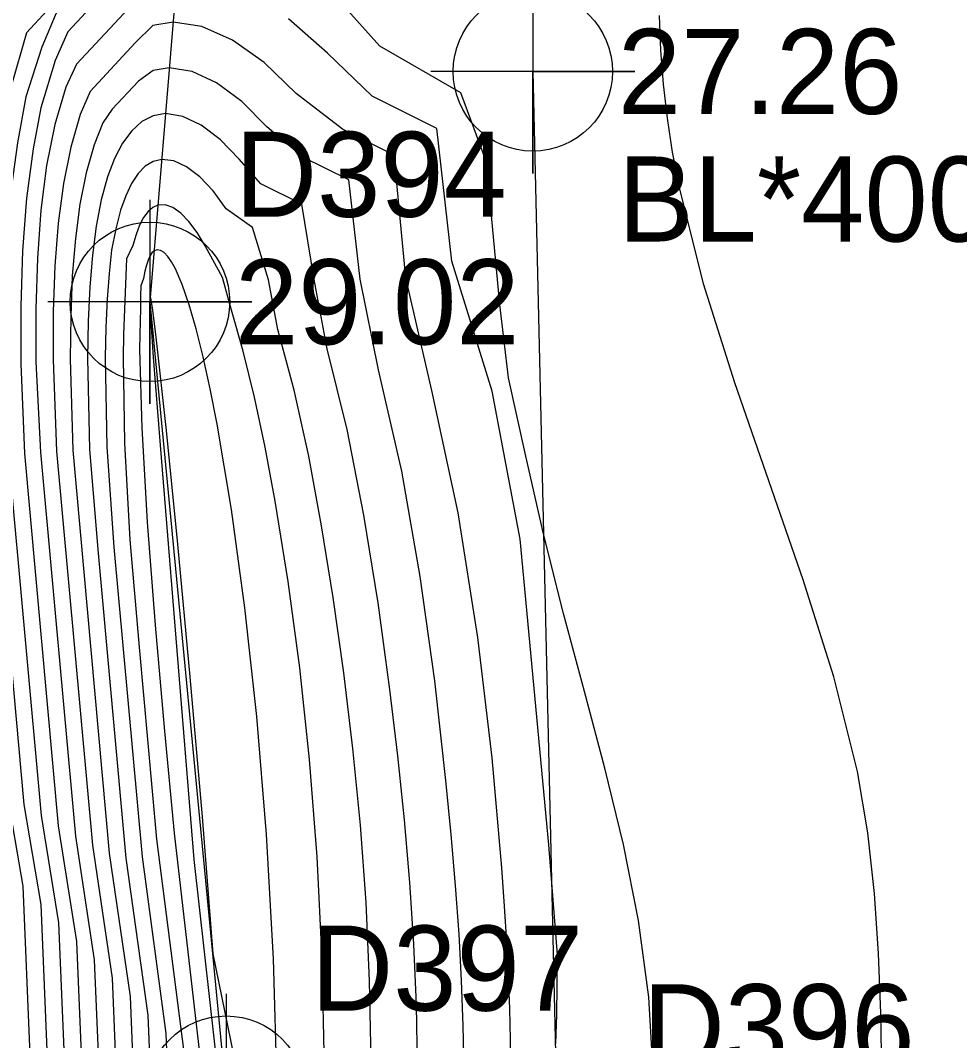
# Model space of a CAD drawing. Extents: x 2356077 to 2359823, y 225951 to 227822.
# Drawn here: x 2356587.63 to 2356615.24, y 227196.5 to 227226.48 of the extents above; entities that cross this region are included whole.
import ezdxf

# ---------------------------------------------------------------- set-up
doc = ezdxf.new("R2010")
doc.units = 0
for name, color, linetype in [('DTM Contours Major', 7, 'Continuous'), ('DTM Contours Minor', 7, 'Continuous'), ('Exist DTM Breakline', 7, 'Continuous'), ('Exist DTM Breakline Cogo Comment', 7, 'Continuous'), ('Exist DTM Breakline Cogo Elevation', 7, 'Continuous'), ('Exist DTM Breakline Cogo Number', 7, 'Continuous'), ('Exist DTM Breakline Cogo Point CELL', 7, 'Continuous')]:
    doc.layers.add(name, color=color, linetype=linetype)

msp = doc.modelspace()

# ---------------------------------------------------------------- linework, layer by layer
at = {"layer": 'DTM Contours Major'}
for points in [[(2356589.008, 227227.424), (2356587.813, 227226.121), (2356587.349, 227224.513), (2356587.22, 227221.462), (2356587.053, 227219.76), (2356586.932, 227217.945), (2356586.884, 227216.067), (2356586.915, 227213.59), (2356587.041, 227211.067), (2356587.733, 227203.437), (2356588.228, 227200.499), (2356588.6, 227191.455)], [(2356600.672, 227195.646), (2356600.65, 227196.936), (2356600.602, 227198.26), (2356600.527, 227199.63), (2356600.425, 227201.059), (2356600.296, 227202.56), (2356600.142, 227204.144), (2356599.813, 227207.067), (2356599.387, 227210.142), (2356598.842, 227213.235), (2356598.157, 227216.213), (2356597.616, 227218.881), (2356597.282, 227221.794), (2356595.936, 227222.463), (2356594.88, 227223.351), (2356594.139, 227224.1), (2356593.397, 227224.646), (2356592.68, 227224.979), (2356592.008, 227225.086), (2356591.532, 227225.01), (2356591.099, 227224.698), (2356590.332, 227223.875), (2356590.055, 227223.469), (2356589.796, 227222.822), (2356589.562, 227222.003), (2356589.38, 227221.084), (2356589.247, 227220.072), (2356589.157, 227218.973), (2356589.109, 227217.793), (2356589.096, 227216.538), (2356589.17, 227213.847), (2356590.244, 227202.01), (2356590.855, 227197.789), (2356591.048, 227193.105)], [(2356594.167, 227194.791), (2356593.296, 227199.05), (2356592.981, 227203.077), (2356592.625, 227207.194), (2356592.262, 227211.085), (2356591.928, 227214.43), (2356591.625, 227217.171), (2356591.522, 227217.968), (2356591.473, 227218.274), (2356591.452, 227218.363), (2356591.444, 227218.376), (2356591.436, 227218.355), (2356591.434, 227218.196), (2356591.438, 227218.088), (2356591.534, 227216.589), (2356591.735, 227213.999), (2356592.355, 227206.4), (2356592.725, 227201.818), (2356593.483, 227195.078)]]:
    msp.add_lwpolyline(points, dxfattribs=at)
at = {"layer": 'DTM Contours Minor'}
for points in [[(2356591.548, 227228.857), (2356589.021, 227226.143), (2356588.652, 227225.301), (2356588.227, 227223.908), (2356588.005, 227222.711), (2356587.812, 227221.256), (2356587.693, 227219.71), (2356587.64, 227218.083), (2356587.643, 227216.386), (2356587.749, 227213.755), (2356588.742, 227202.809), (2356589.279, 227199.415), (2356589.579, 227192.115)], [(2356591.515, 227227.595), (2356589.277, 227225.193), (2356588.964, 227224.524), (2356588.641, 227223.425), (2356588.4, 227222.215), (2356588.232, 227220.902), (2356588.129, 227219.497), (2356588.084, 227218.009), (2356588.088, 227216.447), (2356588.222, 227213.794), (2356589.246, 227202.509), (2356589.804, 227198.873), (2356590.069, 227192.445)], [(2356588.735, 227226.81), (2356588.262, 227225.693), (2356587.789, 227224.237), (2356587.541, 227222.884), (2356587.331, 227221.329), (2356587.205, 227219.688), (2356587.153, 227217.971), (2356587.162, 227216.187), (2356587.282, 227213.652), (2356588.238, 227203.117), (2356588.753, 227199.957), (2356589.09, 227191.785)], [(2356606.244, 227195.395), (2356606.101, 227197.775), (2356605.801, 227200.025), (2356605.359, 227202.263), (2356604.817, 227204.504), (2356604.216, 227206.762), (2356603.599, 227209.053), (2356603.007, 227211.392), (2356602.489, 227213.679), (2356601.984, 227215.975), (2356601.726, 227218.137), (2356601.332, 227222.317), (2356600.577, 227224.357), (2356598.199, 227225.727), (2356597.086, 227226.964)], [(2356587.04, 227226.516), (2356586.907, 227224.774), (2356586.829, 227222.918), (2356586.664, 227221.139), (2356586.498, 227219.431), (2356586.413, 227217.642), (2356586.398, 227215.777), (2356586.457, 227213.466), (2356586.581, 227211.092), (2356586.781, 227208.68), (2356587.22, 227203.836), (2356587.702, 227201.041), (2356588.11, 227191.125)], [(2356602.047, 227195.656), (2356602.04, 227196.527), (2356602.018, 227197.434), (2356601.981, 227198.385), (2356601.929, 227199.387), (2356601.863, 227200.449), (2356601.781, 227201.579), (2356601.496, 227204.807), (2356601.078, 227208.348), (2356600.498, 227212.01), (2356599.724, 227215.603), (2356598.959, 227218.913), (2356598.62, 227222.522), (2356597.1, 227223.284), (2356595.733, 227224.332), (2356594.801, 227225.244), (2356593.867, 227225.906), (2356592.963, 227226.306), (2356592.119, 227226.431), (2356591.524, 227226.333), (2356591.001, 227225.819), (2356589.677, 227224.397), (2356589.389, 227223.712), (2356589.109, 227222.753), (2356588.896, 227221.687), (2356588.744, 227220.521), (2356588.646, 227219.264), (2356588.597, 227217.923), (2356588.592, 227216.507), (2356588.696, 227213.826), (2356589.747, 227202.24), (2356590.33, 227198.331), (2356590.558, 227192.775)], [(2356603.369, 227196.41), (2356603.398, 227197.255), (2356603.414, 227198.123), (2356603.419, 227199.017), (2356603.167, 227202.256), (2356602.322, 227211.231), (2356601.5, 227215.581), (2356600.314, 227219.408), (2356599.875, 227223.306), (2356597.971, 227224.252), (2356596.66, 227225.521), (2356595.515, 227226.532)], [(2356615.934, 227181.068), (2356614.844, 227183.13), (2356614.067, 227185.234), (2356613.549, 227187.367), (2356613.233, 227189.511), (2356613.065, 227191.651), (2356612.989, 227193.773), (2356612.922, 227197.303), (2356612.86, 227199.058), (2356612.744, 227200.82), (2356612.545, 227202.601), (2356612.237, 227204.41), (2356611.544, 227207.191), (2356610.645, 227210.038), (2356608.63, 227215.835), (2356607.714, 227218.737), (2356606.993, 227221.611), (2356606.803, 227222.612), (2356606.65, 227223.61), (2356606.535, 227224.609), (2356606.456, 227225.612), (2356606.415, 227226.623)], [(2356599.306, 227195.766), (2356599.272, 227197.547), (2356599.196, 227199.335), (2356599.077, 227201.144), (2356598.919, 227202.985), (2356598.723, 227204.871), (2356598.492, 227206.813), (2356598.145, 227209.364), (2356597.73, 227211.94), (2356597.235, 227214.457), (2356596.645, 227216.83), (2356596.271, 227218.865), (2356595.902, 227221.08), (2356594.701, 227221.676), (2356594.064, 227222.401), (2356593.503, 227222.983), (2356592.944, 227223.406), (2356592.404, 227223.662), (2356591.897, 227223.742), (2356591.536, 227223.677), (2356591.205, 227223.507), (2356590.904, 227223.237), (2356590.635, 227222.873), (2356590.398, 227222.421), (2356590.195, 227221.888), (2356590.007, 227221.206), (2356589.859, 227220.436), (2356589.748, 227219.582), (2356589.67, 227218.648), (2356589.624, 227217.639), (2356589.608, 227216.559), (2356589.664, 227213.885), (2356589.911, 227210.928), (2356590.734, 227201.861), (2356591.381, 227197.247), (2356591.538, 227193.435)], [(2356597.942, 227195.909), (2356597.898, 227198.25), (2356597.791, 227200.556), (2356597.625, 227202.832), (2356597.405, 227205.08), (2356597.137, 227207.307), (2356596.825, 227209.517), (2356596.487, 227211.625), (2356596.107, 227213.673), (2356595.679, 227215.614), (2356595.199, 227217.4), (2356594.925, 227218.857), (2356594.456, 227220.398), (2356593.682, 227220.944), (2356593.294, 227221.47), (2356592.901, 227221.885), (2356592.513, 227222.182), (2356592.138, 227222.355), (2356591.785, 227222.397), (2356591.533, 227222.336), (2356591.301, 227222.196), (2356591.088, 227221.979), (2356590.897, 227221.69), (2356590.726, 227221.331), (2356590.578, 227220.906), (2356590.439, 227220.359), (2356590.312, 227219.731), (2356590.243, 227219.047), (2356590.181, 227218.286), (2356590.142, 227217.46), (2356590.125, 227216.572), (2356590.172, 227213.951), (2356590.382, 227210.996), (2356591.207, 227201.896), (2356591.906, 227196.705), (2356592.027, 227193.765)], [(2356596.573, 227195.69), (2356596.503, 227198.877), (2356596.351, 227201.9), (2356596.128, 227204.76), (2356595.842, 227207.456), (2356595.504, 227209.987), (2356595.122, 227212.354), (2356594.829, 227213.935), (2356594.516, 227215.412), (2356594.184, 227216.763), (2356593.832, 227217.968), (2356593.572, 227218.925), (2356593.061, 227219.856), (2356592.824, 227220.248), (2356592.584, 227220.569), (2356592.345, 227220.814), (2356592.11, 227220.979), (2356591.885, 227221.059), (2356591.674, 227221.052), (2356591.523, 227220.984), (2356591.382, 227220.862), (2356591.253, 227220.688), (2356591.136, 227220.463), (2356591.032, 227220.188), (2356590.94, 227219.865), (2356590.754, 227219.47), (2356590.66, 227217.252), (2356590.647, 227216.576), (2356590.693, 227214.057), (2356590.847, 227211.212), (2356591.124, 227208.061), (2356591.636, 227202.417), (2356592.432, 227196.162)], [(2356595.179, 227195.104), (2356595.075, 227198.901), (2356594.87, 227202.559), (2356594.583, 227206.019), (2356594.232, 227209.221), (2356593.837, 227212.106), (2356593.414, 227214.616), (2356593.21, 227215.655), (2356593.005, 227216.59), (2356592.8, 227217.416), (2356592.595, 227218.127), (2356592.391, 227218.717), (2356592.189, 227219.179), (2356592.076, 227219.383), (2356591.964, 227219.543), (2356591.856, 227219.656), (2356591.752, 227219.722), (2356591.654, 227219.74), (2356591.563, 227219.707), (2356591.498, 227219.647), (2356591.438, 227219.557), (2356591.383, 227219.436), (2356591.334, 227219.287), (2356591.29, 227219.108), (2356591.251, 227218.9), (2356591.172, 227218.68), (2356591.16, 227218.381), (2356591.162, 227218.01), (2356591.147, 227217.644), (2356591.138, 227217.249), (2356591.135, 227216.822), (2356591.197, 227214.506), (2356591.361, 227211.737), (2356591.595, 227208.703), (2356591.868, 227205.593), (2356592.149, 227202.595), (2356592.957, 227195.62)]]:
    msp.add_lwpolyline(points, dxfattribs=at)
at = {"layer": 'Exist DTM Breakline'}
for points in [[(2356575.82, 227148.639), (2356572.681, 227182.58), (2356573.963, 227212.061), (2356577.748, 227240.207), (2356581.287, 227243.662), (2356587.377, 227239.444), (2356592.648, 227232.822), (2356591.439, 227218.21), (2356593.678, 227194.877), (2356594.225, 227153.117)], [(2356602.695, 227224.982), (2356603.426, 227193.155), (2356599.546, 227163.669)]]:
    msp.add_lwpolyline(points, dxfattribs=at)
at = {"layer": 'Exist DTM Breakline Cogo Point CELL'}
for points in [[(2356602.695, 227227.982), (2356602.695, 227221.982), (2356602.695, 227224.982), (2356605.695, 227224.982), (2356599.695, 227224.982)], [(2356591.439, 227221.21), (2356591.439, 227215.21), (2356591.439, 227218.21), (2356594.439, 227218.21), (2356588.439, 227218.21)], [(2356593.678, 227197.877), (2356593.678, 227191.877), (2356593.678, 227194.877), (2356596.678, 227194.877), (2356590.678, 227194.877)]]:
    msp.add_lwpolyline(points, dxfattribs=at)
for centre in [(2356602.695, 227224.982), (2356591.439, 227218.21), (2356593.678, 227194.877)]:
    msp.add_circle(centre, 2.344, dxfattribs=at)

# ---------------------------------------------------------------- texts
at = {"layer": 'Exist DTM Breakline Cogo Comment'}
msp.add_text('BL*40052', height=2.5, dxfattribs=at).set_placement((2356605.195, 227219.983))
at = {"layer": 'Exist DTM Breakline Cogo Elevation'}
for s, p in [('27.26', (2356605.195, 227223.733)), ('29.02', (2356593.939, 227216.96))]:
    msp.add_text(s, height=2.5, dxfattribs=at).set_placement(p)
at = {"layer": 'Exist DTM Breakline Cogo Number'}
for s, p in [('D394', (2356593.939, 227220.71)), ('D397', (2356596.178, 227197.377)), ('D396', (2356605.926, 227195.655))]:
    msp.add_text(s, height=2.5, dxfattribs=at).set_placement(p)

doc.saveas('drawing.dxf')
